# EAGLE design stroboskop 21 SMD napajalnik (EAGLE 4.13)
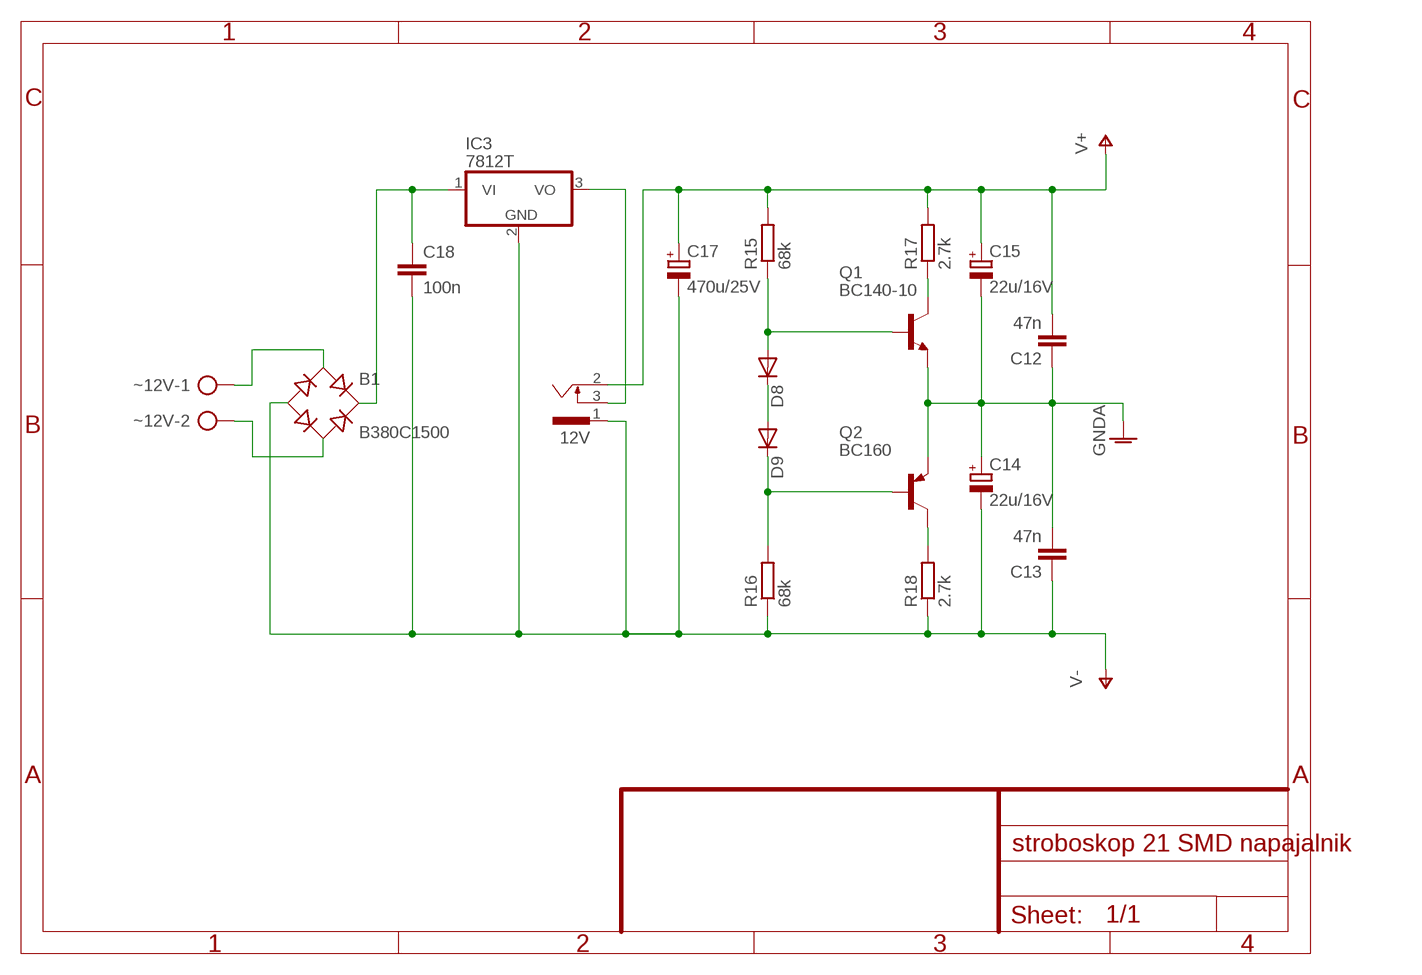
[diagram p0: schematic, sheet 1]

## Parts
12V  733989-55  [733989-5]
B1  B380C1500  RB1A  [RB1A]
C12  47n  C-EU050-025X075  [C050-025X075]
C13  47n  C-EU050-025X075  [C050-025X075]
C14  22u/16V  CPOL-EUE5-10.5  [E5-10,5]
C15  22u/16V  CPOL-EUE5-10.5  [E5-10,5]
C17  470u/25V  CPOL-EUE5-10.5  [E5-10,5]
C18  100n  C-EU050-025X075  [C050-025X075]
D8  DIODE-SOD80C  [SOD80C]
D9  DIODE-SOD80C  [SOD80C]
IC3  7812T  [TO220H]
Q1  BC140-10  [TO39]
Q2  BC160  [TO39]
R15  68k  R-EU_M1206  [M1206]
R16  68k  R-EU_M1206  [M1206]
R17  2.7k  R-EU_M1206  [M1206]
R18  2.7k  R-EU_M1206  [M1206]
~12V  AK300/2  [AK300/2]

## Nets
GNDA: C12.1 C13.2 C14.+ C15.- Q1.1(E) Q2.1(E)
N$33: Q1.3(C) R17.1
N$34: Q2.3(C) R18.2
N$35: D8.A Q1.2(B) R15.1
N$36: D8.C D9.A
N$37: D9.C Q2.2(B) R16.2
N$42: B1.AC1 ~12V.1
N$43: B1.AC2 ~12V.2
N$44: B1.+ C18.1 IC3.1(VI)
N$46: 12V.3 IC3.3(VO)
V+: 12V.2 C12.2 C15.+ C17.+ R15.2 R17.2
V-: 12V.1 B1.- C13.1 C14.- C17.- C18.2 IC3.2(GND) R16.1 R18.1

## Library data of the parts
12V = con-conrad:733989-55: FEMALE PRINT CONNECTOR Außen-Ø 4,2 mm, Innen 1.1 mm FUK HING Industries, distributor Conrad
B1 = rectifier:RB1A: RECTIFIER 1 A
C12 C13 C18 = rcl:C-EU: CAPACITOR, European symbol
C14 C15 C17 = rcl:CPOL-EU: POLARIZED CAPACITOR, European symbol
D8 D9 = diode:DIODE-: DIODE
IC3 = linear:78*: Positive VOLTAGE REGULATOR
Q1 = transistor-npn:BC140-10: NPN Transistor
Q2 = transistor-pnp:BC160*: PNP Transistror
R15-R18 = rcl:R-EU_: RESISTOR, European symbol
~12V = con-ptr500:AK300/2: CONNECTOR

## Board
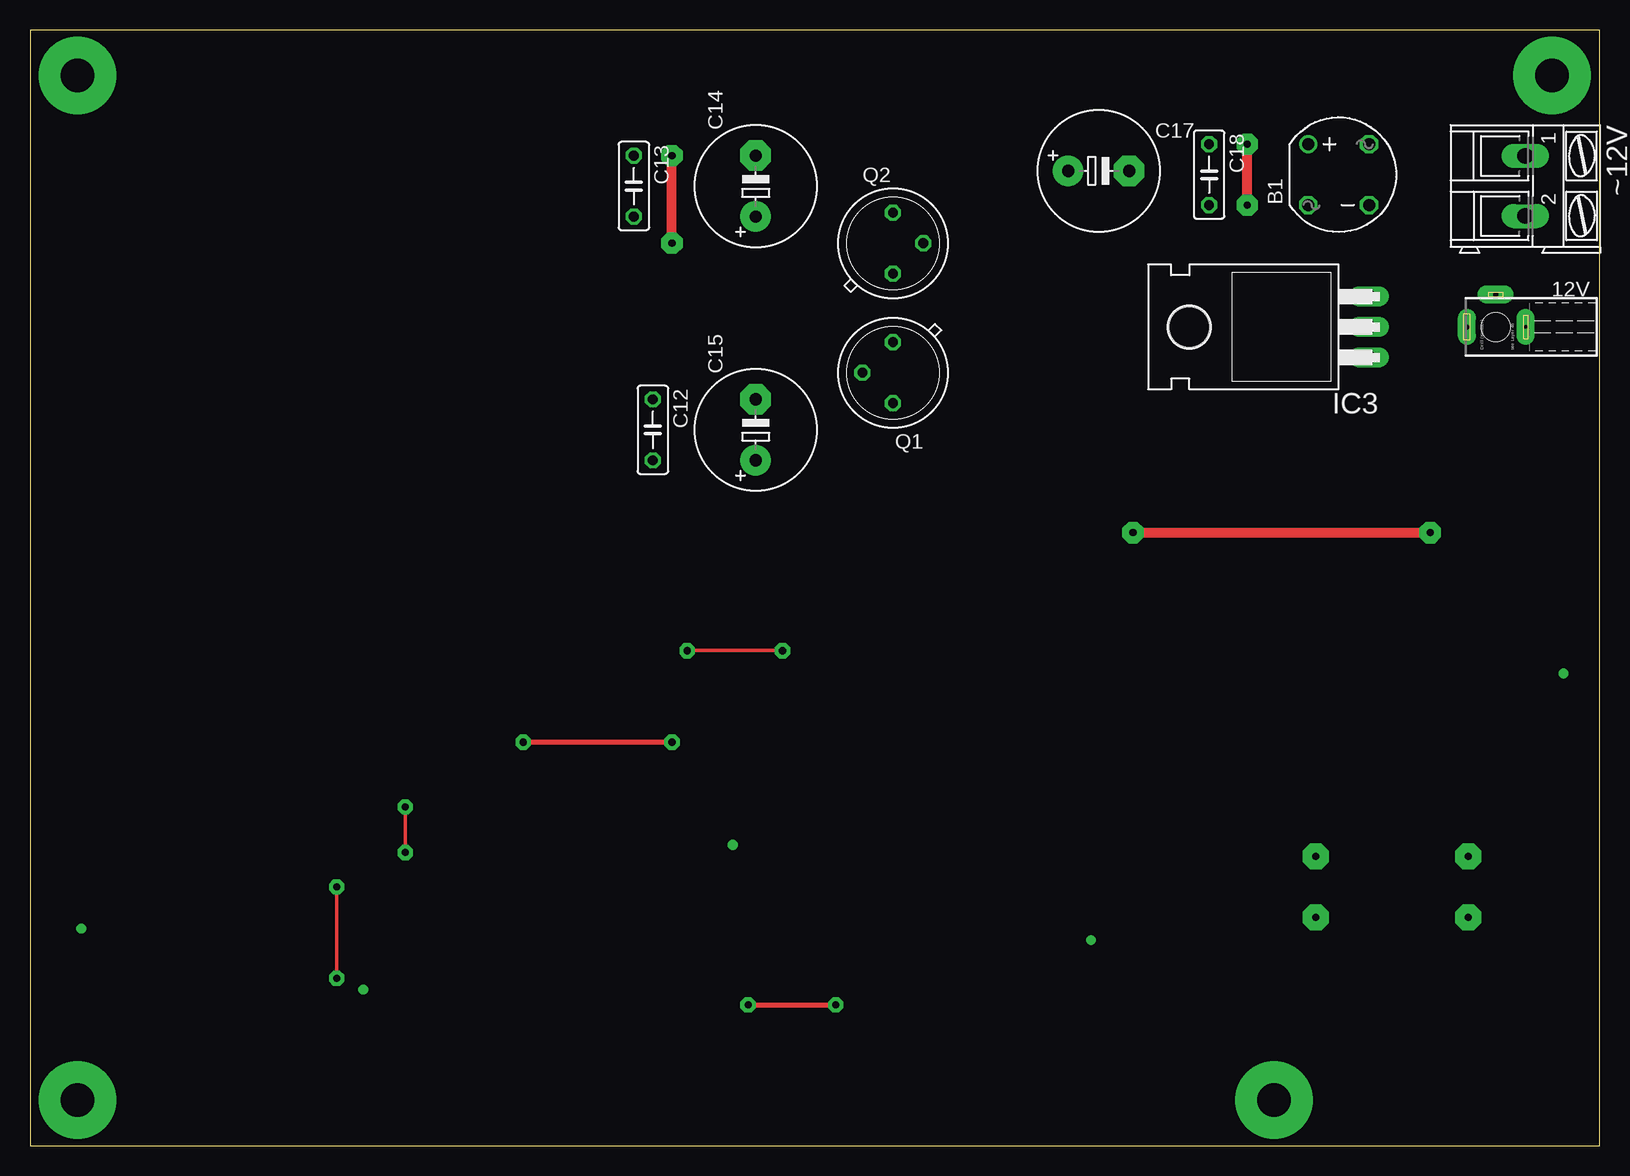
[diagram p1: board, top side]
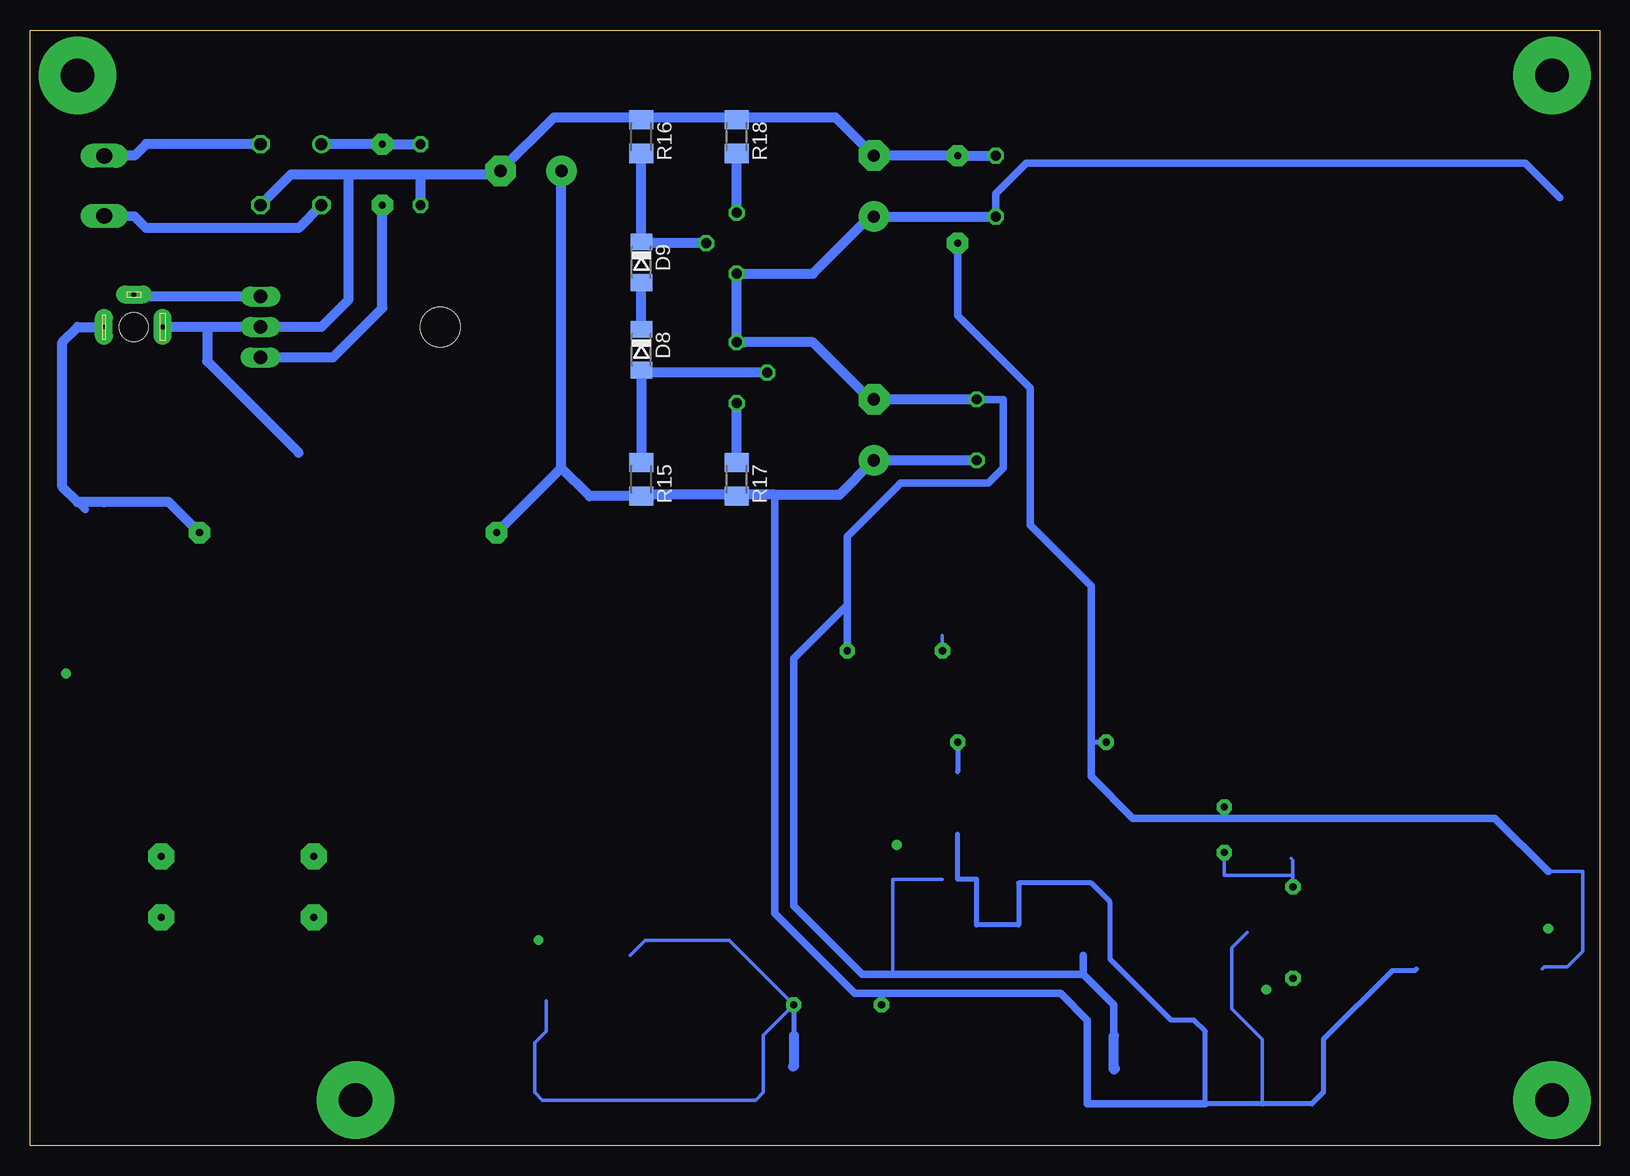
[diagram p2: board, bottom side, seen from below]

Size 130.8 x 93.02 mm. Coordinates in mm from the lower left corner, seen from the top.
Outline: 0,0 130.8,0 130.8,93.02 0,93.02 0,0
Copper layers (1*16): Top 0.035mm / dielectric 1.5mm / Bottom 0.035mm
Design rules "default": minimum track width 12mil, minimum drill 5mil, track to track 10mil, track to pad 10mil, pad to pad 10mil, via to via 10mil, smd to smd 10mil, copper to edge 40mil, drill to drill 8mil, minimum pad ring 10mil, minimum via ring 8mil, stop-mask expansion 4mil, vias tented up to drill 0mil, thermal gap 10mil

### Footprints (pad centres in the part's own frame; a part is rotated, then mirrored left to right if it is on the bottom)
733989-5 = drill 0.4 pad 1.5 long: 1 0,5.82; 3 2.7,3.42 | drill 0.3 pad 1.5 long: 2 0,0.92 | hole 2.4: 0,3.42
RB1A = drill 1.016 round: + -2.54,2.54 | drill 1.016 octagon: - 2.54,-2.54; AC1 2.54,2.54; AC2 -2.54,-2.54
C050-025X075 = drill 0.813 octagon: 1 -2.54,0; 2 2.54,0
E5-10,5 = drill 1.016 pad 2.54 round: + -2.54,0 | drill 1.016 pad 2.54 octagon: - 2.54,0
SOD80C = smd 1.4 x 1.8: A 1.7,0; C -1.7,0
TO220H = drill 1.118 long: 1 -2.54,-10.16; 2 0,-10.16; 3 2.54,-10.16 | hole 3.302: 0,4.826
TO39 = drill 0.813 octagon: 1 0,-2.54; 2 2.54,0; 3 0,2.54
M1206 = smd 1.6 x 2: 1 -1.4,0; 2 1.4,0
AK300/2 = drill 1.321 long: 1 -2.515,0; 2 2.489,0

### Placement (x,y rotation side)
12V  125.56,68.26 90 top
B1  109.06,80.96 0 top
C12  51.91,59.68 270 top
C13  50.32,80.01 270 top
C14  60.48,80.01 90 top
C15  60.48,59.68 90 top
C17  89.05,81.28 0 top
C18  98.26,80.96 270 top
D8  79.84,66.35 270 bottom
D9  79.84,73.66 270 bottom
IC3  101.44,68.26 90 top
Q1  71.91,64.45 180 top
Q2  71.91,75.24 0 top
R15  79.84,55.56 270 bottom
R16  79.84,84.13 270 bottom
R17  71.91,55.56 270 bottom
R18  71.91,84.13 270 bottom
~12V  124.61,80.01 270 top

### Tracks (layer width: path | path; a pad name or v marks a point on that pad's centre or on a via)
GNDA  (via drill 0.6 pad 1.27)
  Top 0.305: v62.7,41.27 v54.76,41.27
  Bottom 0.254: 71.27,66.99 Q1.1 72.23,66.67
  Bottom 0.305: v54.76,41.27 54.76,42.54 | 54.76,22.22 58.89,22.22 58.89,14.28
  Bottom 0.61: 3.33,79.05 6.18,81.91 47.78,81.91 50.32,79.37 C13.2 | C12.1 49.68,62.22 49.68,56.51 50.95,55.24 58.25,55.24 62.7,50.79 62.7,45.08 | 43.01,14.28 43.01,15.87 | 43.01,14.28 58.89,14.28 61.43,14.28 67.15,20 67.15,40.63 62.7,45.08 | 62.7,45.08 v62.7,41.27 | 40.47,9.2 40.47,11.74 43.01,14.28
  Bottom 0.813: C13.2 C14.+ 61.43,76.83 65.56,72.7 Q2.1 Q1.1 | C12.1 C15.- 61.43,62.86 65.56,66.99 71.27,66.99 | 40.39,6.42 40.47,6.34 40.47,9.2
N$33
  Bottom 0.813: R17.1 Q1.3
N$34
  Bottom 0.813: Q2.3 R18.2
N$35
  Bottom 0.254: 79.21,64.45 D8.A
  Bottom 0.813: D8.A R15.1 | Q1.2 79.21,64.45
N$36
  Bottom 0.813: D8.C D9.A
N$37
  Bottom 0.254: 79.21,75.24 D9.C
  Bottom 0.813: Q2.2 79.21,75.24 | D9.C R16.2
N$42
  Bottom 0.813: B1.AC1 121.12,83.5 122.07,82.55 ~12V.1
N$43
  Bottom 0.813: B1.AC2 108.42,76.51 121.12,76.51 122.07,77.47 ~12V.2
N$44  (via drill 0.6 pad 1.78)
  Top 0.813: v101.43,78.42 v101.43,83.5
  Bottom 0.813: IC3.1 105.56,65.72 101.43,69.84 v101.43,78.42 | C18.1 v101.43,83.5 B1.+
N$46
  Bottom 0.813: 12V.3 122.23,70.96 122.39,70.8 IC3.3
N$56  (via drill 0.6 pad 2.18)
  other vias: 107.15,24.12
N$57  (via drill 0.6 pad 2.18)
  other vias: 107.15,19.05
N$58  (via drill 0.6 pad 2.18)
  other vias: 119.85,24.12
N$59  (via drill 0.6 pad 2.18)
  other vias: 119.85,19.05
N$61  (via drill 0 pad 0.81)
  other vias: 58.57,25.08
N$62  (via drill 0 pad 0.81)
  other vias: 88.42,17.14
N$63  (via drill 0 pad 0.81)
  other vias: 127.79,39.36
N$64  (via drill 0 pad 0.81)
  other vias: 4.28,18.09 27.77,13.01
N$65  (via drill 2.8 pad 6.45)
  other vias: 3.96,3.81
N$66  (via drill 2.8 pad 6.45)
  other vias: 103.66,3.81
N$67  (via drill 2.8 pad 6.45)
  other vias: 3.96,89.21
N$68  (via drill 2.8 pad 6.45)
  other vias: 126.84,89.21
V+  (via drill 0.6 pad 1.27, 0.6 pad 1.78)
  Top 0.406: v59.84,11.74 v67.15,11.74
  Top 0.813: v91.91,51.11 v116.67,51.11
  Bottom 0.254: R17.2 72.86,54.29 | 78.89,54.29 R15.2
  Bottom 0.305: 87.78,12.06 87.78,9.52 88.73,8.57 88.73,4.44 88.1,3.81 70.32,3.81 69.68,4.44 69.68,9.2 v67.15,11.74 72.54,17.14 79.53,17.14 80.8,15.87 | 28.09,3.49 28.09,8.88 30.63,11.42 30.63,13.96 30.63,16.51 29.36,17.78
  Bottom 0.406: 53.49,25.97 53.49,22.22 51.9,22.22 51.9,18.41 48.41,18.41 48.41,21.9 42.38,21.9 40.79,20.32 40.79,15.55 35.71,10.47 33.81,10.47 32.86,9.52 32.86,3.49 28.09,3.49 23.96,3.49 23.01,4.44 23.01,8.88 17.3,14.6 15.39,14.6 15.26,14.73 | v67.15,11.74 67.15,9.2 | 59.84,12.69 v59.84,11.74
  Bottom 0.61: 32.86,3.49 42.7,3.49 42.7,10.47 44.92,12.69 59.84,12.69 62.07,12.69 68.73,19.36 68.73,54.29 | 126.84,53.65 126.2,53.02
  Bottom 0.813: 72.86,54.29 78.89,54.29 | C12.2 C15.+ 63.33,54.29 68.73,54.29 71.91,54.29 R17.2 | 12V.2 126.84,68.26 128.11,66.99 128.11,54.92 126.84,53.65 124.61,53.65 119.21,53.65 v116.67,51.11 | R15.2 84.16,54.16 86.51,56.51 | 86.51,56.51 C17.+ | 86.51,56.51 v91.91,51.11 | 67.23,6.58 67.15,6.66 67.15,9.2
V-  (via drill 0.6 pad 1.27, 0.6 pad 1.78)
  Top 0.305: v25.55,21.59 v25.55,13.96 | v31.27,28.25 v31.27,24.44
  Top 0.406: v41.11,33.65 v53.49,33.65
  Top 0.813: v53.49,75.24 v53.49,82.55
  Bottom 0.254: R18.1 72.86,85.72 | 78.89,85.72 R16.1
  Bottom 0.305: 4.22,22.86 4.28,22.86 1.42,22.86 1.42,16.19 2.69,14.92 4.6,14.92 4.79,14.73 | 25.55,22.54 v25.55,21.59 | 25.55,22.54 31.27,22.54 v31.27,24.44 | 25.68,23.94 25.55,23.81 25.55,22.54 | 31.27,27.3 v31.27,28.25
  Bottom 0.406: v53.49,33.65 53.49,31.17 | 42.38,33.65 v41.11,33.65
  Bottom 0.61: v53.49,75.24 53.49,69.21 47.46,63.18 47.46,51.75 42.38,46.67 42.38,33.65 42.38,30.79 38.89,27.3 31.27,27.3 8.72,27.3 4.28,22.86
  Bottom 0.813: 72.86,85.72 78.89,85.72 | R18.1 72.23,85.72 63.65,85.72 C14.- v53.49,82.55 C13.1 | B1.- 109.06,80.96 104.29,80.96 | 98.26,80.96 91.91,80.96 C17.- 87.15,85.72 79.84,85.72 R16.1 | 98.26,80.96 104.29,80.96 | 98.26,80.96 C18.2 | 116.04,68.26 111.91,68.26 111.59,68.58 IC3.2 106.51,68.26 104.29,70.48 104.29,80.96 | 116.04,68.26 12V.1 | 116.04,68.26 116.04,65.4 108.42,57.78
